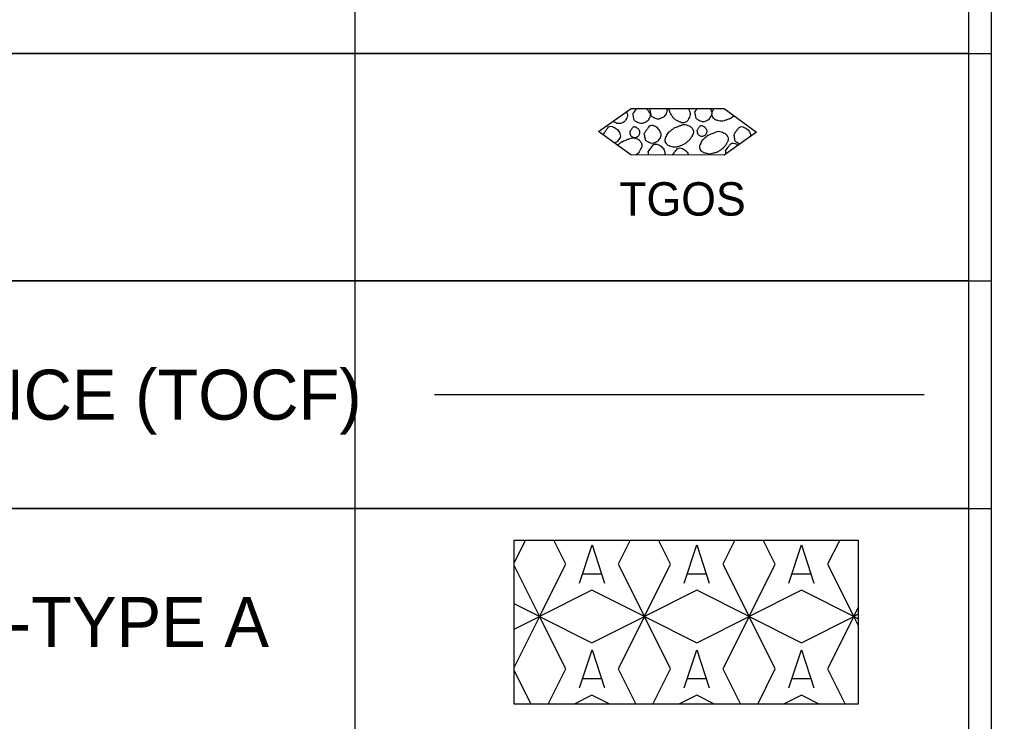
# Model space of a CAD drawing. Extents: x 1.3 to 34, y 0 to 22.5.
# Drawn here: x 16.062 to 18.2, y 12.856 to 14.4 of the extents above; entities that cross this region are included whole.
import ezdxf

# ---------------------------------------------------------------- set-up
doc = ezdxf.new("R2010")
doc.units = 0
for name, color, linetype in [('G-ANNO-SYMB', 7, 'Continuous'), ('G-ANNO-TABL', 7, 'Continuous'), ('G-USER-LINE', 7, 'Continuous')]:
    doc.layers.add(name, color=color, linetype=linetype)

msp = doc.modelspace()

# ---------------------------------------------------------------- linework, layer by layer
at = {"layer": 'G-ANNO-SYMB'}
for p, q in [((16.975, 13.575), (18.052, 13.575)), ((17.1747, 13.2553), (17.15, 13.2058)), ((17.2635, 13.2024), (17.237, 13.2553)), ((17.4051, 13.2553), (17.3787, 13.2024)), ((17.4939, 13.2024), (17.4674, 13.2553)), ((17.6355, 13.2553), (17.6091, 13.2024)), ((17.7243, 13.2024), (17.6978, 13.2553)), ((17.8659, 13.2553), (17.8395, 13.2024)), ((17.15, 13.1989), (17.2059, 13.0872)), ((17.2059, 13.0872), (17.2635, 13.2024)), ((17.3787, 13.2024), (17.4363, 13.0872)), ((17.4363, 13.0872), (17.4939, 13.2024)), ((17.6091, 13.2024), (17.6667, 13.0872)), ((17.6667, 13.0872), (17.7243, 13.2024)), ((17.8395, 13.2024), (17.8971, 13.0872)), ((17.3419, 13.1802), (17.3002, 13.1802)), ((17.5723, 13.1802), (17.5306, 13.1802)), ((17.8027, 13.1802), (17.761, 13.1802)), ((17.3211, 13.1448), (17.2059, 13.0872)), ((17.4363, 13.0872), (17.3211, 13.1448)), ((17.5515, 13.1448), (17.4363, 13.0872)), ((17.6667, 13.0872), (17.5515, 13.1448)), ((17.7819, 13.1448), (17.6667, 13.0872)), ((17.8971, 13.0872), (17.7819, 13.1448)), ((17.2059, 13.0872), (17.15, 13.1151)), ((17.15, 13.0592), (17.2059, 13.0872)), ((17.2059, 13.0872), (17.15, 12.9754)), ((17.2059, 13.0872), (17.3211, 13.0296)), ((17.2635, 12.972), (17.2059, 13.0872)), ((17.3211, 13.0296), (17.4363, 13.0872)), ((17.4363, 13.0872), (17.3787, 12.972)), ((17.4363, 13.0872), (17.5515, 13.0296)), ((17.4939, 12.972), (17.4363, 13.0872)), ((17.5515, 13.0296), (17.6667, 13.0872)), ((17.6667, 13.0872), (17.6091, 12.972)), ((17.6667, 13.0872), (17.7819, 13.0296)), ((17.7243, 12.972), (17.6667, 13.0872)), ((17.7819, 13.0296), (17.8971, 13.0872)), ((17.8971, 13.0872), (17.8395, 12.972)), ((17.8971, 13.0872), (17.9068, 13.1066)), ((17.9068, 13.092), (17.8971, 13.0872)), ((17.8971, 13.0872), (17.9068, 13.0823)), ((17.9068, 13.0678), (17.8971, 13.0872)), ((17.15, 12.9685), (17.1869, 12.8947)), ((17.2249, 12.8947), (17.2635, 12.972)), ((17.3787, 12.972), (17.4173, 12.8947)), ((17.4553, 12.8947), (17.4939, 12.972)), ((17.6091, 12.972), (17.6477, 12.8947)), ((17.6857, 12.8947), (17.7243, 12.972)), ((17.8395, 12.972), (17.8781, 12.8947)), ((17.3419, 12.9498), (17.3002, 12.9498)), ((17.5723, 12.9498), (17.5306, 12.9498)), ((17.8027, 12.9498), (17.761, 12.9498)), ((17.3211, 12.9144), (17.2818, 12.8947)), ((17.3603, 12.8947), (17.3211, 12.9144)), ((17.5515, 12.9144), (17.5122, 12.8947)), ((17.5907, 12.8947), (17.5515, 12.9144)), ((17.7819, 12.9144), (17.7426, 12.8947)), ((17.8211, 12.8947), (17.7819, 12.9144))]:
    msp.add_line(p, q, dxfattribs=at)
for points in [[(17.4072, 14.2046), (17.612, 14.204), (17.6833, 14.1526), (17.6117, 14.1016), (17.4069, 14.1021), (17.3357, 14.1536)], [(17.15, 13.2553), (17.9068, 13.2553), (17.9068, 12.8947), (17.15, 12.8947)]]:
    msp.add_lwpolyline(points, close=True, dxfattribs=at)
for points in [[(17.2936, 13.1604), (17.3214, 13.2444), (17.3485, 13.1604)], [(17.524, 13.1604), (17.5518, 13.2444), (17.5789, 13.1604)], [(17.7544, 13.1604), (17.7822, 13.2444), (17.8093, 13.1604)], [(17.2936, 12.93), (17.3214, 13.014), (17.3485, 12.93)], [(17.524, 12.93), (17.5518, 13.014), (17.5789, 12.93)], [(17.7544, 12.93), (17.7822, 13.014), (17.8093, 12.93)]]:
    msp.add_lwpolyline(points, dxfattribs=at)
for points, degree in [([(17.4402, 14.2045), (17.443, 14.2021), (17.4451, 14.199), (17.4469, 14.196), (17.4494, 14.1916), (17.4488, 14.1852), (17.4457, 14.1805), (17.4432, 14.1768), (17.44, 14.1743), (17.4361, 14.1728), (17.4313, 14.1709), (17.4254, 14.1714), (17.4207, 14.174), (17.4177, 14.1756), (17.4142, 14.1774), (17.4135, 14.1806), (17.4128, 14.1846), (17.412, 14.1885), (17.4112, 14.1925)], 3), ([(17.4112, 14.1925), (17.414, 14.1965), (17.4168, 14.2005), (17.4196, 14.2045)], 2), ([(17.4851, 14.2044), (17.4866, 14.2), (17.4854, 14.195), (17.4826, 14.1905), (17.4801, 14.1866), (17.4768, 14.1844), (17.473, 14.1828), (17.4684, 14.1808), (17.4627, 14.1809), (17.4582, 14.1834), (17.4551, 14.1852), (17.4517, 14.1873), (17.451, 14.1906), (17.4503, 14.1946), (17.4495, 14.1985), (17.4487, 14.2025)], 3), ([(17.5334, 14.2042), (17.5341, 14.2024), (17.5348, 14.2005), (17.5355, 14.1987), (17.5375, 14.1937), (17.5364, 14.1879), (17.5343, 14.1826), (17.5329, 14.1791), (17.5305, 14.1762), (17.5271, 14.1743), (17.523, 14.172), (17.5175, 14.1729), (17.5135, 14.175), (17.5076, 14.178), (17.5019, 14.1812), (17.498, 14.1869), (17.4942, 14.1925), (17.4914, 14.1982), (17.4895, 14.2044)], 3), ([(17.5474, 14.1969), (17.5491, 14.1993), (17.5508, 14.2018), (17.5525, 14.2042)], 2), ([(17.5808, 14.2041), (17.5817, 14.2029), (17.5825, 14.2016), (17.5831, 14.2004), (17.5855, 14.1959), (17.5843, 14.1898), (17.5813, 14.1849), (17.5789, 14.181), (17.5757, 14.1783), (17.5718, 14.1766), (17.5672, 14.1746), (17.5614, 14.1751), (17.5569, 14.1778), (17.5539, 14.1796), (17.5504, 14.1817), (17.5498, 14.185), (17.549, 14.1889), (17.5482, 14.1929), (17.5474, 14.1969)], 3), ([(17.6342, 14.188), (17.6338, 14.1877), (17.6334, 14.1874), (17.6331, 14.1871), (17.6277, 14.1829), (17.621, 14.1806), (17.6146, 14.1783), (17.6092, 14.1763), (17.603, 14.1762), (17.5973, 14.1777), (17.5933, 14.1788), (17.5897, 14.181), (17.5873, 14.1849), (17.5845, 14.1892), (17.5849, 14.1944), (17.5867, 14.1986), (17.5875, 14.2004), (17.5883, 14.2023), (17.5892, 14.2041)], 3), ([(17.3967, 14.1971), (17.397, 14.1966), (17.3973, 14.196), (17.3975, 14.1955), (17.3998, 14.1909), (17.3988, 14.1849), (17.3957, 14.18), (17.3933, 14.1762), (17.3901, 14.1736), (17.3862, 14.1723), (17.3814, 14.1708), (17.3757, 14.1712), (17.3713, 14.1736), (17.3699, 14.1743), (17.3685, 14.1751), (17.3672, 14.176)], 3), ([(17.3462, 14.148), (17.3494, 14.1526), (17.3526, 14.1571), (17.3558, 14.1617), (17.3586, 14.1658), (17.3662, 14.1648), (17.3707, 14.1623), (17.3752, 14.1597), (17.379, 14.1561), (17.3813, 14.1515), (17.3838, 14.1468), (17.3834, 14.1403), (17.3801, 14.1361), (17.3776, 14.1327), (17.3748, 14.1298), (17.3711, 14.128)], 3), ([(17.404, 14.1532), (17.4059, 14.156), (17.4079, 14.1588), (17.4099, 14.1616), (17.4118, 14.1641), (17.4166, 14.1638), (17.4194, 14.1621), (17.422, 14.1605), (17.4241, 14.1583), (17.4254, 14.1556), (17.4268, 14.1527), (17.4267, 14.1489), (17.4248, 14.1461), (17.4232, 14.1438), (17.4212, 14.1422), (17.4188, 14.1413), (17.416, 14.1402), (17.4126, 14.1403), (17.4099, 14.1419), (17.4081, 14.143), (17.4062, 14.1442), (17.4057, 14.1461), (17.4051, 14.1485), (17.4045, 14.1509), (17.404, 14.1532)], 3), ([(17.4355, 14.1496), (17.4389, 14.1541), (17.4422, 14.1587), (17.4456, 14.1632), (17.4486, 14.1672), (17.4561, 14.1669), (17.4605, 14.1644), (17.4651, 14.1618), (17.4688, 14.1578), (17.4712, 14.1531), (17.4735, 14.1483), (17.4732, 14.1422), (17.4699, 14.1376), (17.4674, 14.134), (17.4642, 14.1314), (17.4604, 14.1299), (17.4556, 14.128), (17.4497, 14.1286), (17.4449, 14.1311), (17.442, 14.1327), (17.4384, 14.1345), (17.4378, 14.1377), (17.437, 14.1417), (17.4363, 14.1456), (17.4355, 14.1496)], 3), ([(17.5003, 14.1607), (17.5063, 14.1631), (17.5122, 14.1655), (17.5182, 14.1678), (17.5234, 14.1699), (17.5294, 14.1685), (17.5349, 14.166), (17.5383, 14.1644), (17.5408, 14.162), (17.5426, 14.1588), (17.5448, 14.1547), (17.5441, 14.1492), (17.5419, 14.1451), (17.5389, 14.1395), (17.5354, 14.1346), (17.53, 14.1303), (17.5241, 14.1256), (17.5182, 14.1228), (17.5115, 14.1208), (17.506, 14.1192), (17.4999, 14.1192), (17.4943, 14.1209), (17.4905, 14.122), (17.4873, 14.124), (17.4848, 14.1275), (17.4818, 14.1316), (17.4818, 14.1371), (17.4836, 14.1411), (17.4857, 14.1456), (17.4881, 14.1505), (17.492, 14.1536), (17.495, 14.156), (17.498, 14.1584), (17.5009, 14.1607)], 3), ([(17.5515, 14.1558), (17.5535, 14.1586), (17.5555, 14.1614), (17.5575, 14.1641), (17.5592, 14.1666), (17.5637, 14.1662), (17.5664, 14.1647), (17.5691, 14.1632), (17.5714, 14.1609), (17.5729, 14.1582), (17.5744, 14.1553), (17.5743, 14.1515), (17.5723, 14.1486), (17.5707, 14.1464), (17.5687, 14.1447), (17.5663, 14.1439), (17.5635, 14.1429), (17.5601, 14.1434), (17.5574, 14.1451), (17.5556, 14.1462), (17.5538, 14.1474), (17.5533, 14.1493), (17.5527, 14.1515), (17.5521, 14.1536), (17.5515, 14.1558)], 3), ([(17.6336, 14.1473), (17.6367, 14.1518), (17.6399, 14.1564), (17.6431, 14.1609), (17.646, 14.165), (17.6537, 14.1641), (17.658, 14.1615), (17.6623, 14.1589), (17.6665, 14.1557), (17.6687, 14.1508), (17.6698, 14.1483), (17.6703, 14.1458), (17.6701, 14.1433)], 3), ([(17.3866, 14.1313), (17.3926, 14.1336), (17.3986, 14.136), (17.4045, 14.1384), (17.4097, 14.1404), (17.4158, 14.1397), (17.4212, 14.1371), (17.4247, 14.1355), (17.4272, 14.1328), (17.4289, 14.1294), (17.4309, 14.1253), (17.4309, 14.1201), (17.4288, 14.1163), (17.426, 14.1112), (17.4229, 14.106), (17.4184, 14.1021)], 3), ([(17.5764, 14.1457), (17.5824, 14.148), (17.5884, 14.1504), (17.5943, 14.1527), (17.5995, 14.1548), (17.6055, 14.1534), (17.611, 14.1509), (17.6144, 14.1493), (17.6169, 14.147), (17.6187, 14.1438), (17.621, 14.1396), (17.6207, 14.1341), (17.6186, 14.1301), (17.6157, 14.1244), (17.6121, 14.1195), (17.6067, 14.1152), (17.6008, 14.1106), (17.5949, 14.1077), (17.5882, 14.1058), (17.5827, 14.1041), (17.5766, 14.1042), (17.571, 14.1058), (17.5671, 14.1069), (17.5636, 14.1088), (17.5609, 14.1124), (17.5577, 14.1167), (17.5583, 14.1224), (17.5603, 14.1267), (17.5623, 14.1308), (17.5645, 14.1354), (17.5681, 14.1385), (17.5711, 14.1411), (17.5741, 14.1437), (17.577, 14.1462)], 3), ([(17.6466, 14.1264), (17.6451, 14.1269), (17.6438, 14.1275), (17.6424, 14.1282), (17.6394, 14.1299), (17.6358, 14.1321), (17.6353, 14.1354), (17.6347, 14.1393), (17.6341, 14.1433), (17.6336, 14.1473)], 3), ([(17.3771, 14.1237), (17.3775, 14.1241), (17.3779, 14.1244), (17.3783, 14.1248), (17.3813, 14.1271), (17.3843, 14.1295), (17.3872, 14.1319)], 3), ([(17.4449, 14.1091), (17.4481, 14.1135), (17.4512, 14.1178), (17.4544, 14.1222), (17.4574, 14.1262), (17.465, 14.1259), (17.4693, 14.1233), (17.4738, 14.1207), (17.4778, 14.1171), (17.48, 14.112), (17.4814, 14.1087), (17.4818, 14.1052), (17.4811, 14.1019)], 3), ([(17.4985, 14.1019), (17.5013, 14.1058), (17.504, 14.1098), (17.5068, 14.1137), (17.5097, 14.1179), (17.518, 14.1177), (17.5222, 14.1149), (17.5265, 14.112), (17.5307, 14.1083), (17.5329, 14.1035), (17.5332, 14.103), (17.5334, 14.1024), (17.5336, 14.1018)], 3), ([(17.615, 14.111), (17.6182, 14.1156), (17.6214, 14.1202), (17.6246, 14.1247), (17.6275, 14.1289), (17.6356, 14.1279), (17.64, 14.1253), (17.6409, 14.1247), (17.6418, 14.1242), (17.6426, 14.1236)], 3), ([(17.4459, 14.102), (17.4456, 14.1044), (17.4452, 14.1068), (17.4449, 14.1091)], 2), ([(17.6162, 14.1048), (17.6158, 14.1069), (17.6154, 14.109), (17.615, 14.111)], 2)]:
    msp.add_open_spline(points, degree=degree, dxfattribs=at)
at = {"layer": 'G-ANNO-TABL'}
for p, q in [((2, 14.325), (18.2, 14.325)), ((2, 13.825), (18.2, 13.825)), ((2, 13.325), (18.2, 13.325))]:
    msp.add_line(p, q, dxfattribs=at)
msp.add_lwpolyline([(12.8, 7.825), (18.2, 7.825), (18.2, 19.825), (12.8, 19.825)], close=True, dxfattribs=at)
at = {"layer": 'G-USER-LINE'}
for p, q in [((16.8, 14.325), (16.8, 14.825)), ((18.15, 14.325), (18.15, 14.825)), ((16.8, 14.325), (12.85, 14.325)), ((16.8, 13.825), (16.8, 14.325)), ((18.15, 14.325), (16.8, 14.325)), ((18.15, 13.825), (18.15, 14.325)), ((16.8, 13.825), (12.85, 13.825)), ((18.15, 13.825), (16.8, 13.825)), ((16.8, 13.325), (16.8, 13.825)), ((18.15, 13.325), (18.15, 13.825)), ((16.8, 13.325), (12.85, 13.325)), ((18.15, 13.325), (16.8, 13.325)), ((16.8, 12.825), (16.8, 13.325)), ((18.15, 12.825), (18.15, 13.325))]:
    msp.add_line(p, q, dxfattribs=at)

# ---------------------------------------------------------------- texts
at = {"layer": 'G-ANNO-SYMB'}
msp.add_text('TGOS', height=0.07344, dxfattribs=at).set_placement((17.381, 13.9687))
at = {"layer": 'G-ANNO-TABL'}
for s, p in [('TEMPORARY ORANGE CONSTRUCTION FENCE (TOCF)', (12.9, 13.52)), ('TEMPORARY SOIL STABILIZATION MATTING-TYPE A', (12.9, 13.02))]:
    msp.add_text(s, height=0.11, dxfattribs=at).set_placement(p)

doc.saveas('drawing.dxf')
